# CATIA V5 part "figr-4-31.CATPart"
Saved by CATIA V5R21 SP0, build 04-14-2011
Part number: Part1
Bounding box of the stored display mesh (mm): x 0 to 81, y 0 to 160, z -80 to 0
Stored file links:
  D:\CATIA V5R21 E-RESOURCES\CATIA-V5R21\catia-v5r21-prt\c04-catia-v5r20-prt\catia-v5r21-figr-4-30.CATPart
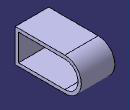
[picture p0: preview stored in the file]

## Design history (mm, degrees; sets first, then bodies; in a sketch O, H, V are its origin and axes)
Body1 (main body)
  Sketch1 on yz-plane, origin (0, 0, 0), H (0, 1, 0), V (0, 0, 1)
    line L1 (0, 0) -> (0, -80)
    line L2 (0, -80) -> (120, -80)
    arc A1 centre (120, -40) radius 40 from (120, -80) to (120, 0) ccw
    line L3 (120, 0) -> (0, 0)
    tangency: A1 L2
  Pad1: profile Sketch1, direction (1, 0, 0), length 81, thin wall 8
